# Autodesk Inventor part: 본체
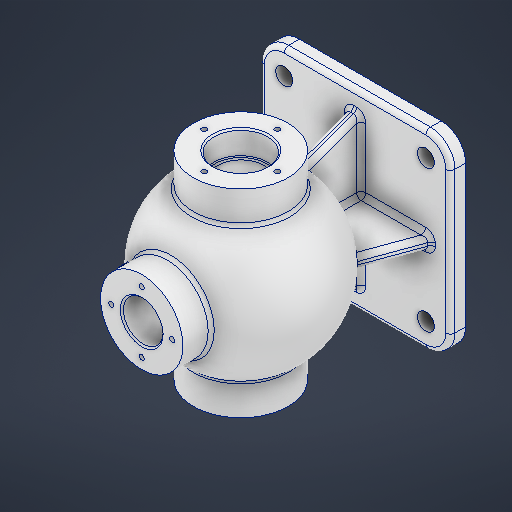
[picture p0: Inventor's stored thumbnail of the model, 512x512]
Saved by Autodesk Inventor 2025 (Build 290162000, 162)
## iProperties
Created: 2025-08
Part Number: 본체
Material: 알루미늄 6061
Document SubType Name: Sheet Metal
Designer: infra15
Density: 2.7 g/cm^3
Sheet Metal Rule: 기본값_mm
Appearance: 알루미늄 - 평지
Mass: 1525.54 g
Surface Area: 1176.74 cm^2
Volume: 565.016 cm^3
Author: infra15
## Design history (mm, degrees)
sketch "스케치1"
  geometry: L1 (-46.5, -62.5)-(46.5, -62.5); L2 (62.5, -46.5)-(62.5, 46.5); L3 (46.5, 62.5)-(-46.5, 62.5); L4 (-62.5, 46.5)-(-62.5, -46.5); L5 (-62.5, -62.5)-(62.5, 62.5); L6 (62.5, -62.5)-(-62.5, 62.5); A1 r 16 centre (46.5, 46.5) between (62.5, 46.5) and (46.5, 62.5); A2 r 16 centre (46.5, -46.5) between (46.5, -62.5) and (62.5, -46.5); A3 r 16 centre (-46.5, -46.5) between (-62.5, -46.5) and (-46.5, -62.5); A4 r 16 centre (-46.5, 46.5) between (-46.5, 62.5) and (-62.5, 46.5); 1 further point
  constraints: 12 end point, 8 point on circle, 8 point on line, 8 tangent, 4 centre point, 3 equal radius, 2 midpoint, 2 parallel, 1 horizontal, 1 perpendicular
  dimensions: "d0" = 125 distance of L6.end L5.end; "d1" = 125 distance of L5.end L6.start; "d2" = 16 radius of A1
extrude "돌출1" new body sketch "스케치1" distance "d3" = 10; taper "d4" = 0 deg
sketch "스케치2"
  geometry: L1 (46.5, -46.5)-(-46.5, -46.5); L2 (-46.5, -46.5)-(-46.5, 46.5); L3 (-46.5, 46.5)-(46.5, 46.5); L4 (46.5, 46.5)-(46.5, -46.5); L5 (46.5, -46.5)-(-46.5, 46.5); L6 (-46.5, -46.5)-(46.5, 46.5); C1 r 5.5 at (-46.5, 46.5); C2 r 5.5 at (46.5, 46.5); C3 r 5.5 at (46.5, -46.5); C4 r 5.5 at (-46.5, -46.5); 1 further point
  constraints: 12 end point, 4 centre point, 4 coincident, 2 midpoint, 2 parallel, 1 horizontal, 1 perpendicular
  dimensions: "d5" = 11 diameter of C1; "d6" = 11 diameter of C2; "d7" = 11 diameter of C3; "d8" = 11 diameter of C4; "d9" = 93 distance of L2.end L3.end; "d10" = 93 distance of L1.end L2.end
extrude "돌출2" cut sketch "스케치2" extent not by distance; stored distance "d11" = 0; taper "d12" = 0 deg
node "작업 평면1"
sketch "스케치3"
  geometry: L1 (0, 54)-(0, -54); L2 (0, 59.486)-(0, -58.647); L3 (-46.5, -62.5)-(46.5, -62.5) reference; L4 (10, -42.849)-(10, 42.849); A1 r 54 centre (0, 0) between (0, -54) and (0, 54); A2 r 44 centre (0, 0) between (10, -42.849) and (10, 42.849); 2 further points
  constraints: 6 end point, 4 point on circle, 2 centre point, 1 coincident, 1 midpoint, 1 perpendicular, 1 vertical, 1 vertical alignment, 1 other
  dimensions: "d14" = 108 diameter of A1; "d16" = 10 radial gap between concentric circles of A1 A2
revolve "회전1" sketch "스케치3" stored, may be unused: angle "d15" = 360 deg
node "작업 평면2"
sketch "스케치5"
  geometry: C1 r 10 at (0, 85) reference; C2 r 31 at (0, 85); 1 further point
  constraints: 1 centre point, 1 coincident
  dimensions: "d18" = 62 diameter of C2
extrude "돌출3" join sketch "스케치5" distance "d19" = 11; taper "d20" = 0 deg
feature "면 삭제1"
sketch "스케치9"
  geometry: C1 r 10 at (0, 0) reference; C2 r 15 at (0, 0); 1 further point
  constraints: 1 centre point, 1 coincident
  dimensions: "d28" = 30 diameter of C2
extrude "돌출7" cut sketch "스케치9" extent not by distance; stored distance "d29" = 0; taper "d30" = 0 deg
sketch "스케치10"
  geometry: C1 r 15 at (0, 0) reference; C2 r 17.5 at (0, 0); 1 further point
  constraints: 1 centre point, 1 coincident
  dimensions: "d31" = 35 diameter of C2
extrude "돌출8" cut sketch "스케치10" distance "d32" = 16; taper "d33" = 0 deg
sketch "스케치11"
  geometry: C1 r 17.5 at (0, 0) reference; 1 further point
extrude "돌출9" cut sketch "스케치11" distance "d34" = 16; taper "d35" = 0 deg
node "작업 평면3"
sketch "스케치12"
  geometry: C1 r 27 at (0, 0); 1 further point
  constraints: 1 centre point, 1 coincident
  dimensions: "d37" = 54 diameter of C1
extrude "돌출10" join sketch "스케치12" stored distance "d38" = 16; taper "d39" = 0 deg
sketch "스케치13"
  geometry: C1 r 13 at (0, 0); 1 further point
  constraints: 1 centre point, 1 coincident
  dimensions: "d40" = 26 diameter of C1
extrude "돌출11" cut sketch "스케치13" distance "d41" = 40.75; taper "d42" = 0 deg
sketch "스케치14"
  geometry: C1 r 15 at (0, 0) reference; A1 r 24 centre (0, 0) between (0, -24) and (-24, 0); 3 further points
  constraints: 4 point on circle, 1 centre point, 1 coincident
  dimensions: "d43" = 48 diameter of A1
hole "구멍1" sketch "스케치14" at (-24, 0), (24, 0), (0, 24), (0, -24) diameter "d44" = 3.242; stored, may be unused: countersink angle "d48" = 90 deg, drill point angle "d50" = 118 deg; dims "d45" = 12, "d46" = 4, "d47" = 2, "d49" = 15
sketch "스케치15"
  geometry: C1 r 1.621 at (0, 24) reference; C2 r 1.621 at (-24, 0) reference; C3 r 1.621 at (0, -24) reference; C4 r 1.621 at (24, 0) reference; 1 further point
hole "구멍2" sketch "스케치15" at (0, 24), (-24, 0), (0, -24), (24, 0) diameter "d51" = 3.242; stored, may be unused: countersink angle "d55" = 90 deg, drill point angle "d57" = 118 deg; dims "d52" = 12, "d53" = 4, "d54" = 2, "d56" = 15
sketch "스케치16"
  geometry: C1 r 13 at (0, 0) reference; A1 r 20 centre (0, 0) between (0, 20) and (20, 0); 3 further points
  constraints: 4 point on circle, 1 centre point, 1 coincident
  dimensions: "d58" = 40 diameter of A1
hole "구멍3" sketch "스케치16" at (0, 20), (20, 0), (-20, 0), (0, -20) diameter "d59" = 3.242; stored, may be unused: countersink angle "d63" = 90 deg, drill point angle "d65" = 118 deg; dims "d60" = 9, "d61" = 4, "d62" = 2, "d64" = 11
sketch "스케치18"
  geometry: L1 (50.5, 10)-(-50.5, 10); L2 (-50.5, 10)-(-42.857, 31); L3 (-42.857, 31)-(42.857, 31); L4 (42.857, 31)-(50.5, 10); 4 further points
  constraints: 8 end point, 1 horizontal, 1 midpoint, 1 parallel
  dimensions: "d70" = 70 deg angle of L1 L2; "d71" = 70 deg angle of L1 L4; "d72" = 12 distance of point (-62.5, 10) L1.end; "d73" = 12 distance of point (62.5, 10) L1.start; "d74" = 10 distance of point (0, 0) point (0, 10); "d75" = 21 distance between parallel lines of L1 L3
extrude "돌출12" join sketch "스케치18" stored distance "d76" = 8; taper "d77" = 0 deg
feature "면 삭제2"
sketch "스케치19"
  geometry: L1 (-50.5, 10)-(50.5, 10); L2 (50.5, 10)-(42.857, 31); L3 (-50.5, 10)-(-42.857, 31); L4 (-42.857, 31)-(42.857, 31); 3 further points
  constraints: 8 end point, 2 horizontal
  dimensions: "d78" = 12 distance of point (62.5, 10) L1.end; "d79" = 12 distance of point (-62.5, 10) L1.start; "d80" = 10 distance from line of point (0, 0) L1; "d81" = 70 deg angle of L1 L3; "d82" = 70 deg angle of L1 L2; "d83" = 21 distance between parallel lines of L1 L4
extrude "돌출13" join sketch "스케치19" stored distance "d84" = 8; taper "d85" = 0 deg
feature "면 삭제3"
feature "면 삭제4"
fillet "모깎기1" dims "d86" = 3
fillet "모깎기2" dims "d87" = 3
node "작업 평면4"
sketch "스케치20"
  geometry: L1 (-20.562, 144.002)-(20.916, 144.002); L2 (20.916, 144.002)-(20.916, 137.998); L3 (20.916, 137.998)-(-20.562, 137.998); L4 (-20.562, 137.998)-(-20.562, 144.002); L5 (27, 150)-(-27, 150) reference; L6 (65, 116)-(65, 54) reference; 3 further points
  constraints: 2 midpoint, 1 horizontal, 2 other
  dimensions: "d89" = 9 distance from line of L5 point (20.916, 141); "d90" = 41.47897 distance of L1.start L1.end; "d91" = 6.00407 distance of L3.end L1.start; "d92" = 64.82299 distance from line of L6 point (0.177, 144.002)
feature "엠보싱1" sketch "스케치20" dims "d93" = 0.5, "d94" = 0, "SeamGap" = 0.01
chamfer "모따기1" distance "d95" = 1; stored, may be unused: second distance "d96" = 2, angle "d97" = 45 deg
chamfer "모따기3" distance "d101" = 1; stored, may be unused: second distance "d102" = 2, angle "d103" = 45 deg
chamfer "모따기5" distance "d107" = 1; stored, may be unused: second distance "d108" = 2, angle "d109" = 45 deg
fillet "모깎기3" dims "d110" = 0.6
fillet "모깎기4" dims "d111" = 0.6
feature "ζ耀θ耀κ耀μ耀ξ耀π耀ς耀τ耀" dims "d0" = 125, "d1" = 125, "d2" = 16, "d3" = 10, "d4" = 0, "d5" = 11, "d6" = 11, "d7" = 11, "d8" = 11, "d9" = 93, "d10" = 93, "d11" = 0, "d12" = 0, "d13" = 85, "d14" = 108, "d15" = 360 deg, "d16" = 10, "d17" = 54, "d18" = 62, "d19" = 11, "d20" = 0, "d28" = 30, "d29" = 0, "d30" = 0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
node "솔리드1"
mirror "미러1"
feature "A9D066F2-1C7D-4E18-AEED-F7BC21143FA4" dims "d44" = 3.242, "d45" = 12, "d46" = 4, "d47" = 2, "d48" = 90 deg, "d49" = 15, "d50" = 118 deg
